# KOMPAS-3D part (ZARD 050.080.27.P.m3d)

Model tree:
1. Булева операция:1
2. Булева операция:2
3. Булева операция:3
4. Булева операция:4
5. Булева операция:5
6. Булева операция:6
7. Булева операция:7
8. Булева операция:8
9. Булева операция:9
10. Булева операция:10
11. Булева операция:11
12. Булева операция:12
13. Булева операция:13
14. Булева операция:14
15. Булева операция:15
16. Булева операция:16
17. Булева операция:17
18. Булева операция:18
19. Булева операция:19
20. Булева операция:20
21. Булева операция:21
22. Булева операция:22

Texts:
  ООО ИК Энерпред-Ярдос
